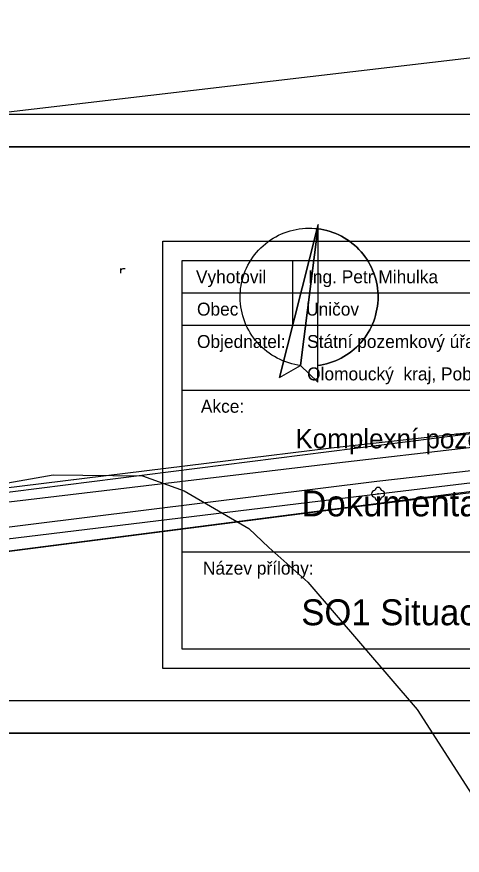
# Model space of a CAD drawing. Extents: x -555887 to -552101, y -1100251 to -1096546.
# Drawn here: x -554433.8 to -554365.1, y -1097989.9 to -1097860.4 of the extents above; entities that cross this region are included whole.
import ezdxf

# ---------------------------------------------------------------- set-up
doc = ezdxf.new("R2010")
doc.units = 0
for name, color, linetype in [('PARCELY_silnice', 7, 'Continuous'), ('ram_HC1', 7, 'Continuous'), ('ram_VC4', 7, 'Continuous'), ('vrstevnice', 7, 'Continuous'), ('ZSST', 7, 'Continuous'), ('zájem', 7, 'Continuous')]:
    doc.layers.add(name, color=color, linetype=linetype)

msp = doc.modelspace()

# ---------------------------------------------------------------- linework, layer by layer
at = {"layer": 'PARCELY_silnice'}
msp.add_lwpolyline([(-554794.85, -1097983), (-554503.64, -1097942.69), (-554487.31, -1097940.43), (-554340.94, -1097921.89), (-554338.17, -1097921.77), (-554275.98, -1097914.73), (-554275.16, -1097920.72), (-554273.32, -1097934.1), (-554278.86, -1097925.79), (-554281.83, -1097923.16), (-554489.26, -1097949.91), (-554499.05, -1097951.29), (-554795.02, -1097992.98), (-554799.97, -1097996.99), (-554801.13, -1097979.06)], close=True, dxfattribs=at)
at = {"layer": 'ram_HC1'}
for p, q in [((-554391.29, -1097898.05), (-554391.29, -1097908.05)), ((-554408.29, -1097903.05), (-554288.29, -1097903.05)), ((-554408.29, -1097908.05), (-554288.29, -1097908.05)), ((-554408.29, -1097918.05), (-554228.29, -1097918.05)), ((-554408.29, -1097943.05), (-554228.29, -1097943.05))]:
    msp.add_line(p, q, dxfattribs=at)
for points in [[(-554578.37, -1097626.82), (-554215.29, -1097626.82), (-554215.29, -1097971.05), (-554578.37, -1097971.05)], [(-554573.37, -1097631.82), (-554220.29, -1097631.82), (-554220.29, -1097966.05), (-554573.37, -1097966.05)], [(-554411.29, -1097895.05), (-554225.29, -1097895.05), (-554225.29, -1097961.05), (-554411.29, -1097961.05)], [(-554408.29, -1097898.05), (-554228.29, -1097898.05), (-554228.29, -1097958.05), (-554408.29, -1097958.05)]]:
    msp.add_lwpolyline(points, close=True, dxfattribs=at)
for points in [[(-554578.37, -1097971.05), (-554215.29, -1097971.05), (-554215.29, -1097626.82), (-554578.37, -1097626.82), (-554578.37, -1097971.05)], [(-554573.37, -1097631.82), (-554220.29, -1097631.82), (-554220.29, -1097966.05), (-554573.37, -1097966.05), (-554573.37, -1097631.82)]]:
    msp.add_lwpolyline(points, dxfattribs=at)
at = {"layer": 'ram_VC4'}
for p, q in [((-554393.26, -1097916.11), (-554387.46, -1097893.12)), ((-554387.38, -1097893.12), (-554390.03, -1097914.25)), ((-554387.46, -1097893.12), (-554387.3, -1097892.48)), ((-554387.46, -1097893.12), (-554387.3, -1097892.48)), ((-554387.46, -1097893.12), (-554387.3, -1097892.48)), ((-554387.46, -1097893.12), (-554387.3, -1097892.48)), ((-554387.46, -1097893.12), (-554387.3, -1097892.48)), ((-554387.46, -1097893.12), (-554387.3, -1097892.48)), ((-554387.46, -1097893.12), (-554387.3, -1097892.48)), ((-554387.46, -1097893.12), (-554387.3, -1097892.48)), ((-554387.38, -1097893.12), (-554387.3, -1097892.48)), ((-554387.38, -1097893.12), (-554387.3, -1097892.48)), ((-554387.38, -1097893.12), (-554387.3, -1097892.48)), ((-554387.38, -1097893.12), (-554387.3, -1097892.48)), ((-554387.38, -1097893.12), (-554387.3, -1097892.48)), ((-554387.38, -1097893.12), (-554387.3, -1097892.48)), ((-554387.38, -1097893.12), (-554387.3, -1097892.48)), ((-554387.38, -1097893.12), (-554387.3, -1097892.48)), ((-554387.36, -1097916.85), (-554387.3, -1097892.48)), ((-554390.03, -1097914.24), (-554387.36, -1097916.85))]:
    msp.add_line(p, q, dxfattribs=at)
for points in [[(-554287.63, -1097875.47), (-554644.63, -1097875.47), (-554644.63, -1098505.47), (-554287.63, -1098505.47)], [(-554292.63, -1097880.47), (-554639.63, -1097880.47), (-554639.63, -1098500.47), (-554292.63, -1098500.47)], [(-554393.26, -1097916.11), (-554390.03, -1097914.25), (-554387.38, -1097893.12), (-554387.46, -1097893.12)], [(-554393.26, -1097916.11), (-554390.03, -1097914.25), (-554387.38, -1097893.12), (-554387.46, -1097893.12)], [(-554393.26, -1097916.11), (-554390.03, -1097914.25), (-554387.38, -1097893.12), (-554387.46, -1097893.12)], [(-554393.26, -1097916.11), (-554390.03, -1097914.25), (-554387.38, -1097893.12), (-554387.46, -1097893.12)], [(-554393.26, -1097916.11), (-554390.03, -1097914.25), (-554387.38, -1097893.12), (-554387.46, -1097893.12)], [(-554393.26, -1097916.11), (-554390.03, -1097914.25), (-554387.38, -1097893.12), (-554387.46, -1097893.12)], [(-554393.26, -1097916.11), (-554390.03, -1097914.25), (-554387.38, -1097893.12), (-554387.46, -1097893.12)], [(-554393.26, -1097916.11), (-554390.03, -1097914.25), (-554387.38, -1097893.12), (-554387.46, -1097893.12)], [(-554387.46, -1097893.12), (-554387.44, -1097893.12), (-554387.42, -1097893.12), (-554387.4, -1097893.12), (-554387.38, -1097893.13), (-554387.38, -1097893.12), (-554387.3, -1097892.48), (-554387.46, -1097893.12), (-554387.46, -1097893.12)], [(-554387.46, -1097893.12), (-554387.44, -1097893.12), (-554387.42, -1097893.12), (-554387.4, -1097893.12), (-554387.38, -1097893.13), (-554387.38, -1097893.12), (-554387.3, -1097892.48), (-554387.46, -1097893.12), (-554387.46, -1097893.12)], [(-554387.46, -1097893.12), (-554387.44, -1097893.12), (-554387.42, -1097893.12), (-554387.4, -1097893.12), (-554387.38, -1097893.13), (-554387.38, -1097893.12), (-554387.3, -1097892.48), (-554387.46, -1097893.12), (-554387.46, -1097893.12)], [(-554387.46, -1097893.12), (-554387.44, -1097893.12), (-554387.42, -1097893.12), (-554387.4, -1097893.12), (-554387.38, -1097893.13), (-554387.38, -1097893.12), (-554387.3, -1097892.48), (-554387.46, -1097893.12), (-554387.46, -1097893.12)], [(-554387.46, -1097893.12), (-554387.44, -1097893.12), (-554387.42, -1097893.12), (-554387.4, -1097893.12), (-554387.38, -1097893.13), (-554387.38, -1097893.12), (-554387.3, -1097892.48), (-554387.46, -1097893.12), (-554387.46, -1097893.12)], [(-554387.46, -1097893.12), (-554387.44, -1097893.12), (-554387.42, -1097893.12), (-554387.4, -1097893.12), (-554387.38, -1097893.13), (-554387.38, -1097893.12), (-554387.3, -1097892.48), (-554387.46, -1097893.12), (-554387.46, -1097893.12)], [(-554387.46, -1097893.12), (-554387.44, -1097893.12), (-554387.42, -1097893.12), (-554387.4, -1097893.12), (-554387.38, -1097893.13), (-554387.38, -1097893.12), (-554387.3, -1097892.48), (-554387.46, -1097893.12), (-554387.46, -1097893.12)], [(-554387.46, -1097893.12), (-554387.44, -1097893.12), (-554387.42, -1097893.12), (-554387.4, -1097893.12), (-554387.38, -1097893.13), (-554387.38, -1097893.12), (-554387.3, -1097892.48), (-554387.46, -1097893.12), (-554387.46, -1097893.12)]]:
    msp.add_lwpolyline(points, close=True, dxfattribs=at)
for points in [[(-554287.63, -1097875.47), (-554644.63, -1097875.47), (-554644.63, -1098505.47), (-554287.63, -1098505.47), (-554287.63, -1097875.47)], [(-554292.63, -1098500.47), (-554639.63, -1098500.47), (-554639.63, -1097880.47), (-554292.63, -1097880.47), (-554292.63, -1098500.47)], [(-554390.03, -1097914.24), (-554390.44, -1097914.19), (-554390.91, -1097914.1), (-554391.38, -1097913.99), (-554391.84, -1097913.86), (-554392.3, -1097913.7), (-554392.75, -1097913.53), (-554393.19, -1097913.34), (-554393.62, -1097913.13), (-554394.04, -1097912.89), (-554394.45, -1097912.64), (-554394.85, -1097912.37), (-554395.24, -1097912.09), (-554395.61, -1097911.78), (-554395.97, -1097911.46), (-554396.31, -1097911.13), (-554396.64, -1097910.78), (-554396.96, -1097910.41), (-554397.25, -1097910.03), (-554397.53, -1097909.64), (-554397.79, -1097909.23), (-554398.03, -1097908.82), (-554398.25, -1097908.39), (-554398.46, -1097907.95), (-554398.64, -1097907.51), (-554398.8, -1097907.06), (-554398.94, -1097906.6), (-554399.06, -1097906.13), (-554399.16, -1097905.66), (-554399.24, -1097905.19), (-554399.3, -1097904.71), (-554399.34, -1097904.23), (-554399.35, -1097903.75), (-554399.34, -1097903.27), (-554399.31, -1097902.79), (-554399.27, -1097902.38), (-554399.21, -1097901.97), (-554399.12, -1097901.49), (-554399.01, -1097901.02), (-554398.88, -1097900.56), (-554398.73, -1097900.1), (-554398.56, -1097899.66), (-554398.36, -1097899.21), (-554398.15, -1097898.78), (-554397.92, -1097898.36), (-554397.67, -1097897.95), (-554397.4, -1097897.55), (-554397.12, -1097897.16), (-554396.81, -1097896.79), (-554396.49, -1097896.43), (-554396.16, -1097896.09), (-554395.81, -1097895.76), (-554395.44, -1097895.44), (-554395.06, -1097895.15), (-554394.67, -1097894.87), (-554394.27, -1097894.61), (-554393.85, -1097894.37), (-554393.42, -1097894.14), (-554392.99, -1097893.94), (-554392.54, -1097893.76), (-554392.09, -1097893.59), (-554391.63, -1097893.45), (-554391.17, -1097893.33), (-554390.7, -1097893.23), (-554390.22, -1097893.15), (-554389.74, -1097893.09), (-554389.26, -1097893.06), (-554388.78, -1097893.04), (-554388.3, -1097893.05), (-554387.82, -1097893.08), (-554387.41, -1097893.12)], [(-554387.3, -1097893.14), (-554386.89, -1097893.2), (-554386.42, -1097893.29), (-554385.95, -1097893.4), (-554385.48, -1097893.54), (-554385.03, -1097893.7), (-554384.58, -1097893.87), (-554384.13, -1097894.07), (-554383.7, -1097894.29), (-554383.28, -1097894.53), (-554382.87, -1097894.78), (-554382.47, -1097895.06), (-554382.09, -1097895.35), (-554381.71, -1097895.66), (-554381.36, -1097895.98), (-554381.02, -1097896.33), (-554380.69, -1097896.68), (-554380.38, -1097897.05), (-554380.09, -1097897.44), (-554379.81, -1097897.84), (-554379.56, -1097898.25), (-554379.32, -1097898.67), (-554379.1, -1097899.1), (-554378.9, -1097899.54), (-554378.72, -1097899.99), (-554378.57, -1097900.45), (-554378.43, -1097900.91), (-554378.31, -1097901.38), (-554378.22, -1097901.86), (-554378.15, -1097902.33), (-554378.1, -1097902.82), (-554378.07, -1097903.3), (-554378.06, -1097903.71), (-554378.07, -1097904.13), (-554378.1, -1097904.61), (-554378.16, -1097905.09), (-554378.23, -1097905.57), (-554378.33, -1097906.04), (-554378.44, -1097906.51), (-554378.58, -1097906.97), (-554378.74, -1097907.43), (-554378.92, -1097907.88), (-554379.12, -1097908.32), (-554379.34, -1097908.75), (-554379.58, -1097909.17), (-554379.84, -1097909.58), (-554380.12, -1097909.98), (-554380.41, -1097910.36), (-554380.73, -1097910.73), (-554381.05, -1097911.08), (-554381.4, -1097911.42), (-554381.76, -1097911.75), (-554382.13, -1097912.06), (-554382.52, -1097912.35), (-554382.92, -1097912.62), (-554383.33, -1097912.87), (-554383.75, -1097913.11), (-554384.19, -1097913.32), (-554384.63, -1097913.52), (-554385.08, -1097913.69), (-554385.54, -1097913.85), (-554386, -1097913.98), (-554386.47, -1097914.09), (-554386.95, -1097914.18), (-554387.36, -1097914.24)], [(-554387.36, -1097914.24), (-554386.95, -1097914.18), (-554386.47, -1097914.09), (-554386, -1097913.98), (-554385.54, -1097913.85), (-554385.08, -1097913.69), (-554384.63, -1097913.52), (-554384.19, -1097913.32), (-554383.75, -1097913.11), (-554383.33, -1097912.87), (-554382.92, -1097912.62), (-554382.52, -1097912.35), (-554382.13, -1097912.06), (-554381.76, -1097911.75), (-554381.4, -1097911.42), (-554381.05, -1097911.08), (-554380.73, -1097910.73), (-554380.41, -1097910.36), (-554380.12, -1097909.98), (-554379.84, -1097909.58), (-554379.58, -1097909.17), (-554379.34, -1097908.75), (-554379.12, -1097908.32), (-554378.92, -1097907.88), (-554378.74, -1097907.43), (-554378.58, -1097906.97), (-554378.44, -1097906.51), (-554378.33, -1097906.04), (-554378.23, -1097905.57), (-554378.16, -1097905.09), (-554378.1, -1097904.61), (-554378.07, -1097904.13), (-554378.06, -1097903.71), (-554378.07, -1097903.3), (-554378.1, -1097902.82), (-554378.15, -1097902.33), (-554378.22, -1097901.86), (-554378.31, -1097901.38), (-554378.43, -1097900.91), (-554378.57, -1097900.45), (-554378.72, -1097899.99), (-554378.9, -1097899.54), (-554379.1, -1097899.1), (-554379.32, -1097898.67), (-554379.56, -1097898.25), (-554379.81, -1097897.84), (-554380.09, -1097897.44), (-554380.38, -1097897.05), (-554380.69, -1097896.68), (-554381.02, -1097896.33), (-554381.36, -1097895.98), (-554381.71, -1097895.66), (-554382.09, -1097895.35), (-554382.47, -1097895.06), (-554382.87, -1097894.78), (-554383.28, -1097894.53), (-554383.7, -1097894.29), (-554384.13, -1097894.07), (-554384.58, -1097893.87), (-554385.03, -1097893.7), (-554385.48, -1097893.54), (-554385.95, -1097893.4), (-554386.42, -1097893.29), (-554386.89, -1097893.2), (-554387.3, -1097893.14)], [(-554387.36, -1097914.24), (-554386.95, -1097914.18), (-554386.47, -1097914.09), (-554386, -1097913.98), (-554385.54, -1097913.85), (-554385.08, -1097913.69), (-554384.63, -1097913.52), (-554384.19, -1097913.32), (-554383.75, -1097913.11), (-554383.33, -1097912.87), (-554382.92, -1097912.62), (-554382.52, -1097912.35), (-554382.13, -1097912.06), (-554381.76, -1097911.75), (-554381.4, -1097911.42), (-554381.05, -1097911.08), (-554380.73, -1097910.73), (-554380.41, -1097910.36), (-554380.12, -1097909.98), (-554379.84, -1097909.58), (-554379.58, -1097909.17), (-554379.34, -1097908.75), (-554379.12, -1097908.32), (-554378.92, -1097907.88), (-554378.74, -1097907.43), (-554378.58, -1097906.97), (-554378.44, -1097906.51), (-554378.33, -1097906.04), (-554378.23, -1097905.57), (-554378.16, -1097905.09), (-554378.1, -1097904.61), (-554378.07, -1097904.13), (-554378.06, -1097903.71), (-554378.07, -1097903.3), (-554378.1, -1097902.82), (-554378.15, -1097902.33), (-554378.22, -1097901.86), (-554378.31, -1097901.38), (-554378.43, -1097900.91), (-554378.57, -1097900.45), (-554378.72, -1097899.99), (-554378.9, -1097899.54), (-554379.1, -1097899.1), (-554379.32, -1097898.67), (-554379.56, -1097898.25), (-554379.81, -1097897.84), (-554380.09, -1097897.44), (-554380.38, -1097897.05), (-554380.69, -1097896.68), (-554381.02, -1097896.33), (-554381.36, -1097895.98), (-554381.71, -1097895.66), (-554382.09, -1097895.35), (-554382.47, -1097895.06), (-554382.87, -1097894.78), (-554383.28, -1097894.53), (-554383.7, -1097894.29), (-554384.13, -1097894.07), (-554384.58, -1097893.87), (-554385.03, -1097893.7), (-554385.48, -1097893.54), (-554385.95, -1097893.4), (-554386.42, -1097893.29), (-554386.89, -1097893.2), (-554387.3, -1097893.14)], [(-554387.36, -1097914.24), (-554386.95, -1097914.18), (-554386.47, -1097914.09), (-554386, -1097913.98), (-554385.54, -1097913.85), (-554385.08, -1097913.69), (-554384.63, -1097913.52), (-554384.19, -1097913.32), (-554383.75, -1097913.11), (-554383.33, -1097912.87), (-554382.92, -1097912.62), (-554382.52, -1097912.35), (-554382.13, -1097912.06), (-554381.76, -1097911.75), (-554381.4, -1097911.42), (-554381.05, -1097911.08), (-554380.73, -1097910.73), (-554380.41, -1097910.36), (-554380.12, -1097909.98), (-554379.84, -1097909.58), (-554379.58, -1097909.17), (-554379.34, -1097908.75), (-554379.12, -1097908.32), (-554378.92, -1097907.88), (-554378.74, -1097907.43), (-554378.58, -1097906.97), (-554378.44, -1097906.51), (-554378.33, -1097906.04), (-554378.23, -1097905.57), (-554378.16, -1097905.09), (-554378.1, -1097904.61), (-554378.07, -1097904.13), (-554378.06, -1097903.71), (-554378.07, -1097903.3), (-554378.1, -1097902.82), (-554378.15, -1097902.33), (-554378.22, -1097901.86), (-554378.31, -1097901.38), (-554378.43, -1097900.91), (-554378.57, -1097900.45), (-554378.72, -1097899.99), (-554378.9, -1097899.54), (-554379.1, -1097899.1), (-554379.32, -1097898.67), (-554379.56, -1097898.25), (-554379.81, -1097897.84), (-554380.09, -1097897.44), (-554380.38, -1097897.05), (-554380.69, -1097896.68), (-554381.02, -1097896.33), (-554381.36, -1097895.98), (-554381.71, -1097895.66), (-554382.09, -1097895.35), (-554382.47, -1097895.06), (-554382.87, -1097894.78), (-554383.28, -1097894.53), (-554383.7, -1097894.29), (-554384.13, -1097894.07), (-554384.58, -1097893.87), (-554385.03, -1097893.7), (-554385.48, -1097893.54), (-554385.95, -1097893.4), (-554386.42, -1097893.29), (-554386.89, -1097893.2), (-554387.3, -1097893.14)], [(-554387.36, -1097914.24), (-554386.95, -1097914.18), (-554386.47, -1097914.09), (-554386, -1097913.98), (-554385.54, -1097913.85), (-554385.08, -1097913.69), (-554384.63, -1097913.52), (-554384.19, -1097913.32), (-554383.75, -1097913.11), (-554383.33, -1097912.87), (-554382.92, -1097912.62), (-554382.52, -1097912.35), (-554382.13, -1097912.06), (-554381.76, -1097911.75), (-554381.4, -1097911.42), (-554381.05, -1097911.08), (-554380.73, -1097910.73), (-554380.41, -1097910.36), (-554380.12, -1097909.98), (-554379.84, -1097909.58), (-554379.58, -1097909.17), (-554379.34, -1097908.75), (-554379.12, -1097908.32), (-554378.92, -1097907.88), (-554378.74, -1097907.43), (-554378.58, -1097906.97), (-554378.44, -1097906.51), (-554378.33, -1097906.04), (-554378.23, -1097905.57), (-554378.16, -1097905.09), (-554378.1, -1097904.61), (-554378.07, -1097904.13), (-554378.06, -1097903.71), (-554378.07, -1097903.3), (-554378.1, -1097902.82), (-554378.15, -1097902.33), (-554378.22, -1097901.86), (-554378.31, -1097901.38), (-554378.43, -1097900.91), (-554378.57, -1097900.45), (-554378.72, -1097899.99), (-554378.9, -1097899.54), (-554379.1, -1097899.1), (-554379.32, -1097898.67), (-554379.56, -1097898.25), (-554379.81, -1097897.84), (-554380.09, -1097897.44), (-554380.38, -1097897.05), (-554380.69, -1097896.68), (-554381.02, -1097896.33), (-554381.36, -1097895.98), (-554381.71, -1097895.66), (-554382.09, -1097895.35), (-554382.47, -1097895.06), (-554382.87, -1097894.78), (-554383.28, -1097894.53), (-554383.7, -1097894.29), (-554384.13, -1097894.07), (-554384.58, -1097893.87), (-554385.03, -1097893.7), (-554385.48, -1097893.54), (-554385.95, -1097893.4), (-554386.42, -1097893.29), (-554386.89, -1097893.2), (-554387.3, -1097893.14)], [(-554387.36, -1097914.24), (-554386.95, -1097914.18), (-554386.47, -1097914.09), (-554386, -1097913.98), (-554385.54, -1097913.85), (-554385.08, -1097913.69), (-554384.63, -1097913.52), (-554384.19, -1097913.32), (-554383.75, -1097913.11), (-554383.33, -1097912.87), (-554382.92, -1097912.62), (-554382.52, -1097912.35), (-554382.13, -1097912.06), (-554381.76, -1097911.75), (-554381.4, -1097911.42), (-554381.05, -1097911.08), (-554380.73, -1097910.73), (-554380.41, -1097910.36), (-554380.12, -1097909.98), (-554379.84, -1097909.58), (-554379.58, -1097909.17), (-554379.34, -1097908.75), (-554379.12, -1097908.32), (-554378.92, -1097907.88), (-554378.74, -1097907.43), (-554378.58, -1097906.97), (-554378.44, -1097906.51), (-554378.33, -1097906.04), (-554378.23, -1097905.57), (-554378.16, -1097905.09), (-554378.1, -1097904.61), (-554378.07, -1097904.13), (-554378.06, -1097903.71), (-554378.07, -1097903.3), (-554378.1, -1097902.82), (-554378.15, -1097902.33), (-554378.22, -1097901.86), (-554378.31, -1097901.38), (-554378.43, -1097900.91), (-554378.57, -1097900.45), (-554378.72, -1097899.99), (-554378.9, -1097899.54), (-554379.1, -1097899.1), (-554379.32, -1097898.67), (-554379.56, -1097898.25), (-554379.81, -1097897.84), (-554380.09, -1097897.44), (-554380.38, -1097897.05), (-554380.69, -1097896.68), (-554381.02, -1097896.33), (-554381.36, -1097895.98), (-554381.71, -1097895.66), (-554382.09, -1097895.35), (-554382.47, -1097895.06), (-554382.87, -1097894.78), (-554383.28, -1097894.53), (-554383.7, -1097894.29), (-554384.13, -1097894.07), (-554384.58, -1097893.87), (-554385.03, -1097893.7), (-554385.48, -1097893.54), (-554385.95, -1097893.4), (-554386.42, -1097893.29), (-554386.89, -1097893.2), (-554387.3, -1097893.14)], [(-554387.36, -1097914.24), (-554386.95, -1097914.18), (-554386.47, -1097914.09), (-554386, -1097913.98), (-554385.54, -1097913.85), (-554385.08, -1097913.69), (-554384.63, -1097913.52), (-554384.19, -1097913.32), (-554383.75, -1097913.11), (-554383.33, -1097912.87), (-554382.92, -1097912.62), (-554382.52, -1097912.35), (-554382.13, -1097912.06), (-554381.76, -1097911.75), (-554381.4, -1097911.42), (-554381.05, -1097911.08), (-554380.73, -1097910.73), (-554380.41, -1097910.36), (-554380.12, -1097909.98), (-554379.84, -1097909.58), (-554379.58, -1097909.17), (-554379.34, -1097908.75), (-554379.12, -1097908.32), (-554378.92, -1097907.88), (-554378.74, -1097907.43), (-554378.58, -1097906.97), (-554378.44, -1097906.51), (-554378.33, -1097906.04), (-554378.23, -1097905.57), (-554378.16, -1097905.09), (-554378.1, -1097904.61), (-554378.07, -1097904.13), (-554378.06, -1097903.71), (-554378.07, -1097903.3), (-554378.1, -1097902.82), (-554378.15, -1097902.33), (-554378.22, -1097901.86), (-554378.31, -1097901.38), (-554378.43, -1097900.91), (-554378.57, -1097900.45), (-554378.72, -1097899.99), (-554378.9, -1097899.54), (-554379.1, -1097899.1), (-554379.32, -1097898.67), (-554379.56, -1097898.25), (-554379.81, -1097897.84), (-554380.09, -1097897.44), (-554380.38, -1097897.05), (-554380.69, -1097896.68), (-554381.02, -1097896.33), (-554381.36, -1097895.98), (-554381.71, -1097895.66), (-554382.09, -1097895.35), (-554382.47, -1097895.06), (-554382.87, -1097894.78), (-554383.28, -1097894.53), (-554383.7, -1097894.29), (-554384.13, -1097894.07), (-554384.58, -1097893.87), (-554385.03, -1097893.7), (-554385.48, -1097893.54), (-554385.95, -1097893.4), (-554386.42, -1097893.29), (-554386.89, -1097893.2), (-554387.3, -1097893.14)], [(-554387.36, -1097914.24), (-554386.95, -1097914.18), (-554386.47, -1097914.09), (-554386, -1097913.98), (-554385.54, -1097913.85), (-554385.08, -1097913.69), (-554384.63, -1097913.52), (-554384.19, -1097913.32), (-554383.75, -1097913.11), (-554383.33, -1097912.87), (-554382.92, -1097912.62), (-554382.52, -1097912.35), (-554382.13, -1097912.06), (-554381.76, -1097911.75), (-554381.4, -1097911.42), (-554381.05, -1097911.08), (-554380.73, -1097910.73), (-554380.41, -1097910.36), (-554380.12, -1097909.98), (-554379.84, -1097909.58), (-554379.58, -1097909.17), (-554379.34, -1097908.75), (-554379.12, -1097908.32), (-554378.92, -1097907.88), (-554378.74, -1097907.43), (-554378.58, -1097906.97), (-554378.44, -1097906.51), (-554378.33, -1097906.04), (-554378.23, -1097905.57), (-554378.16, -1097905.09), (-554378.1, -1097904.61), (-554378.07, -1097904.13), (-554378.06, -1097903.71), (-554378.07, -1097903.3), (-554378.1, -1097902.82), (-554378.15, -1097902.33), (-554378.22, -1097901.86), (-554378.31, -1097901.38), (-554378.43, -1097900.91), (-554378.57, -1097900.45), (-554378.72, -1097899.99), (-554378.9, -1097899.54), (-554379.1, -1097899.1), (-554379.32, -1097898.67), (-554379.56, -1097898.25), (-554379.81, -1097897.84), (-554380.09, -1097897.44), (-554380.38, -1097897.05), (-554380.69, -1097896.68), (-554381.02, -1097896.33), (-554381.36, -1097895.98), (-554381.71, -1097895.66), (-554382.09, -1097895.35), (-554382.47, -1097895.06), (-554382.87, -1097894.78), (-554383.28, -1097894.53), (-554383.7, -1097894.29), (-554384.13, -1097894.07), (-554384.58, -1097893.87), (-554385.03, -1097893.7), (-554385.48, -1097893.54), (-554385.95, -1097893.4), (-554386.42, -1097893.29), (-554386.89, -1097893.2), (-554387.3, -1097893.14)]]:
    msp.add_lwpolyline(points, dxfattribs=at)
at = {"layer": 'vrstevnice'}
msp.add_lwpolyline([(-554473.41, -1097939.13), (-554428.19, -1097931.13), (-554414.43, -1097931.27), (-554407.99, -1097933.61), (-554398, -1097939.41), (-554394.92, -1097942.36), (-554388.88, -1097947.7), (-554372.03, -1097967.36), (-554352.37, -1097997.97), (-554339.45, -1098015.94), (-554331.73, -1098025.35), (-554309.12, -1098047.53), (-554282.3, -1098069.86), (-554270.37, -1098078.14), (-554262.5, -1098082.5), (-554238.07, -1098093.73), (-554224.59, -1098097.8), (-554220.66, -1098097.94), (-554208.86, -1098100.05)], dxfattribs=at)
at = {"layer": 'ZSST'}
for points in [[(-554358.6, -1097809.08), (-554357.36, -1097814.61), (-554352.29, -1097836.39), (-554348.54, -1097855.12), (-554348.48, -1097864.55), (-554351.64, -1097865.34), (-554498.38, -1097882.55)], [(-554324.42, -1097887.97), (-554345.37, -1097890.58), (-554341.25, -1097922.13), (-554385.31, -1097927.04), (-554448.92, -1097934.86), (-554492.2, -1097940.22)], [(-554417.75, -1097900), (-554417.75, -1097899.27)], [(-554417.75, -1097899.51), (-554417.64, -1097899.41), (-554417.54, -1097899.35), (-554417.38, -1097899.3), (-554417.23, -1097899.28), (-554417.08, -1097899.27)], [(-554448.96, -1097936.97), (-554385.32, -1097929.41), (-554340.98, -1097924.24), (-554326.44, -1097922.63), (-554276.13, -1097916.58), (-554259.86, -1097914.62)], [(-554293.08, -1097921.69), (-554325.82, -1097926.08), (-554336.83, -1097927.46), (-554378.27, -1097932.19), (-554449.89, -1097941.05)], [(-554672.3, -1097973.03), (-554582.36, -1097960.59), (-554502.42, -1097949.76), (-554457.33, -1097943.69), (-554378.05, -1097934.08), (-554333.06, -1097928.66), (-554286.53, -1097922.6)], [(-554449.75, -1097944.82), (-554380.91, -1097935.99), (-554335.15, -1097930.35), (-554324.95, -1097928.98), (-554293.19, -1097924.91), (-554286.5, -1097924.62), (-554278.58, -1097927.12), (-554273.53, -1097936.68), (-554269.44, -1097947.28), (-554267.11, -1097955.92), (-554265.86, -1097968.03), (-554262.57, -1097991.14), (-554257.46, -1098023.93), (-554235.02, -1098021.57), (-554211.43, -1098018.21), (-554187.78, -1098015.4), (-554185.88, -1098025.67), (-554182.86, -1098048.39)]]:
    msp.add_lwpolyline(points, dxfattribs=at)
msp.add_circle((-554378.05, -1097934.08), 0.05, dxfattribs=at)
for centre, start, end in [((-554378.55, -1097934.08), 89.7942, 269.7942), ((-554378.05, -1097933.58), 359.7942, 179.7942), ((-554377.55, -1097934.08), 269.7942, 89.7942), ((-554378.05, -1097934.58), 179.7942, 359.7942)]:
    msp.add_arc(centre, 0.5, start, end, dxfattribs=at)
at = {"layer": 'zájem'}
msp.add_lwpolyline([(-554487.31, -1097940.43), (-554340.94, -1097921.89), (-554338.17, -1097921.77), (-554275.98, -1097914.73), (-554275.16, -1097920.72), (-554261.03, -1098023.47), (-554242.36, -1098021.18), (-554238.75, -1098020.74), (-554235.08, -1098020.43), (-554187.71, -1098013.33)], dxfattribs=at)

# ---------------------------------------------------------------- texts
at = {"layer": 'ram_HC1'}
for s, height, p in [('Vyhotovil', 2, (-554406.17, -1097901.55)), ('Ing. Petr Mihulka', 2, (-554388.87, -1097901.55)), ('Obec', 2, (-554406.01, -1097906.55)), ('Uničov', 2, (-554389.17, -1097906.55)), ('Objednatel:', 2, (-554406.01, -1097911.55)), ('Státní pozemkový úřad, Krajský pozemkový úřad pro', 2, (-554389.01, -1097911.55)), ('Olomoucký  kraj, Pobočka Olomouc', 2, (-554389.01, -1097916.55)), ('Akce:', 2, (-554405.41, -1097921.55)), ('Komplexní pozemkové úpravy v  k.ú. Nová Dědina u Uničova', 3, (-554390.82, -1097927.05)), ('Dokumentace technického řešení', 4, (-554389.89, -1097937.55)), ('Název přílohy:', 2, (-554405.1, -1097946.55)), ('SO1 Situace - cesta HC1', 4, (-554389.91, -1097954.37))]:
    msp.add_text(s, height=height, dxfattribs=at).set_placement(p)

doc.saveas('drawing.dxf')
